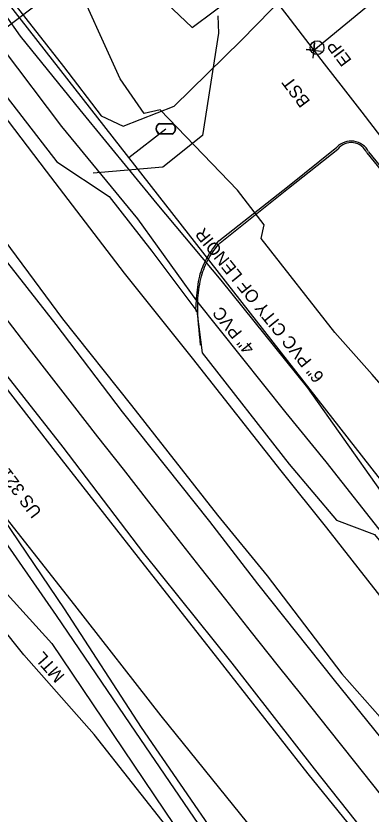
# Model space of a CAD drawing. Extents: x 1263837 to 1268319, y 770628 to 773628.
# Drawn here: x 1266035.1 to 1266148.2, y 772885.8 to 773140.3 of the extents above; entities that cross this region are included whole.
import ezdxf

# ---------------------------------------------------------------- set-up
doc = ezdxf.new("R2010")
doc.units = 0
for name, color, linetype in [('Exist Guardrail', 7, 'Continuous'), ('Exist Guardrail Text', 7, 'Continuous'), ('Exist Property Iron Pin Text', 7, 'Continuous'), ('Exist Roads EOT Text', 7, 'Continuous'), ('Exist Utilities Gas UG Line SUE LOS B', 7, 'Continuous'), ('Exist Utilities Gas UG Line SUE LOS B Text', 7, 'Continuous'), ('Exist Utilities Telephone UG Cable SUE LOS B', 7, 'Continuous'), ('Exist Utilities Telephone UG FO SUE LOS B', 7, 'Continuous'), ('Exist Utilities TV UG Cable SUE LOS B', 7, 'Continuous'), ('Exist Utilities Water Meter CELL', 7, 'Continuous'), ('Exist Utilities Water UG Line SUE LOS B', 7, 'Continuous'), ('Exist Utilities Water UG Line SUE LOS B Text', 7, 'Continuous'), ('Exist Vegetation Woods Line', 7, 'Continuous'), ('Prop Conc 4in Sidewalk', 7, 'Continuous'), ('Prop Drainage Structure Pipe Alternate 42in Label', 7, 'Continuous'), ('Prop Drainage Structure Pipe RCP 60in Class III', 7, 'Continuous'), ('Prop Guardrail', 7, 'Continuous'), ('Prop Horizontal Alignment', 7, 'Continuous'), ('Prop SS Fill Line', 7, 'Continuous'), ('Prop SS Fill Text', 7, 'Continuous'), ('Prop SS Transition Line', 7, 'Continuous'), ('Scratch_Level_2', 7, 'Continuous')]:
    doc.layers.add(name, color=color, linetype=linetype)

# ---------------------------------------------------------------- blocks, each defined once
blk = doc.blocks.new('EXIST PROPERTY IRON PIN')
at = {"layer": 'Prop Conc 4in Sidewalk'}
for radius in [0.0441, 0.00141]:
    blk.add_circle((0, 0), radius, dxfattribs=at)
blk = doc.blocks.new('EXIST UTILITIES WATER METER')
at = {"layer": 'Exist Utilities Water Meter CELL'}
blk.add_line((0, 0), (0, 0), dxfattribs=at)
for points in [[(-0.0408, 0.034), (0.0408, 0.034)], [(-0.0408, 0.0312), (0.0408, 0.0312)], [(0.0408, -0.0312), (-0.0413, -0.0312)], [(0.0408, -0.034), (-0.0413, -0.034)]]:
    blk.add_lwpolyline(points, dxfattribs=at)
for centre, radius, start, end in [((-0.0261, -0.0001), 0.0371, 113.178, 245.9794), ((-0.0259, -0.0001), 0.0347, 115.3009, 243.7824), ((0.0259, 0), 0.0371, 293.6483, 66.3084), ((0.0261, 0), 0.0345, 295.1272, 64.8728)]:
    blk.add_arc(centre, radius, start, end, dxfattribs=at)

msp = doc.modelspace()

# ---------------------------------------------------------------- linework, layer by layer
at = {"layer": 'Exist Guardrail'}
msp.add_lwpolyline([(1266228.54, 772650.54), (1266211.69, 772682.82), (1266194.81, 772714.59), (1266175.46, 772746.94), (1266154.31, 772779.34), (1266140.25, 772802.03), (1266118.08, 772833.91), (1266102.96, 772854.95), (1266084.42, 772880.21), (1266060.03, 772911.15), (1266037.58, 772936.56), (1266030, 772946.04)], dxfattribs=at)
at = {"layer": 'Exist Utilities Gas UG Line SUE LOS B'}
msp.add_lwpolyline([(1266301.62, 772793.02), (1266286.08, 772812.35), (1266262.09, 772842.01), (1266243.02, 772862.25), (1266220.48, 772886.92), (1266195.71, 772919.94), (1266176.51, 772945.32), (1266153.17, 772973.69), (1266133.95, 772998.15), (1266121.2, 773013.77), (1266092.73, 773049.43), (1266073.9, 773075.59), (1266049.68, 773105.06), (1266031.06, 773129.68), (1265993.52, 773179.92)], dxfattribs=at)
at = {"layer": 'Exist Utilities Telephone UG Cable SUE LOS B'}
msp.add_lwpolyline([(1266008.56, 773197.45), (1266009.09, 773190.74), (1266023.54, 773166.8), (1266029.29, 773160.74), (1266032.8, 773146.49), (1266050.24, 773124.2), (1266062.23, 773108.43), (1266069.25, 773105.19), (1266085.51, 773111.53), (1266106.83, 773132.5), (1266131.09, 773157.33)], dxfattribs=at)
at = {"layer": 'Exist Utilities Telephone UG FO SUE LOS B'}
msp.add_lwpolyline([(1266304.09, 772796.95), (1266282.68, 772823.11), (1266259.79, 772851.51), (1266238.02, 772877.36), (1266213.79, 772907.5), (1266201.34, 772925.88), (1266180.67, 772948.97), (1266158.66, 772974.99), (1266151.27, 772988.96), (1266128.09, 773021.69), (1266100.5, 773056.03), (1266080.08, 773080.34), (1266055.55, 773110.31), (1266036.49, 773133.81), (1266017.24, 773161.16), (1265999.24, 773184.25)], dxfattribs=at)
at = {"layer": 'Exist Utilities TV UG Cable SUE LOS B'}
for points in [[(1266037.19, 773158.54), (1266044.2, 773162.17), (1266059.9, 773159.66), (1266076.9, 773150.3), (1266091.19, 773136.64), (1266126.79, 773163.31)], [(1266240.96, 772994.5), (1266228.99, 772979.18), (1266209.71, 772958.7), (1266202.18, 772964.91), (1266178.98, 772993.28), (1266169.92, 773001.47), (1266148.6, 773025.94), (1266136.73, 773039.4), (1266113.26, 773069.37), (1266114.17, 773073.73), (1266105.69, 773084.74), (1266081.06, 773110.3), (1266075.89, 773109.13), (1266068.28, 773120.21), (1266052.48, 773155.25), (1266049, 773158.25), (1266037.19, 773158.54)]]:
    msp.add_lwpolyline(points, dxfattribs=at)
at = {"layer": 'Exist Utilities Water UG Line SUE LOS B'}
msp.add_line((1266071.06, 773095.12), (1266082.82, 773104.31), dxfattribs=at)
msp.add_lwpolyline([(1266307.35, 772809.88), (1266279.02, 772843.7), (1266261.57, 772864.93), (1266241.57, 772883.66), (1266222.07, 772905.04), (1266204.04, 772927.05), (1266182.99, 772951.84), (1266157.71, 772984.17), (1266000.63, 773185.3)], dxfattribs=at)
at = {"layer": 'Exist Vegetation Woods Line'}
msp.add_lwpolyline([(1265737.5, 773343.94), (1265802.41, 773257.53), (1265850.04, 773186.56), (1265870.14, 773156.9), (1265904.49, 773125.47), (1265953.72, 773053.32), (1266023.97, 772964.99), (1266046.51, 772940.19), (1266118.08, 772833.91), (1266225.23, 772647.3), (1266208.09, 772624.42), (1266145.15, 772608.33), (1266113.92, 772610.68), (1266075.12, 772586.17), (1266041.92, 772562.53)], dxfattribs=at)
at = {"layer": 'Prop Drainage Structure Pipe Alternate 42in Label'}
msp.add_line((1266090.78, 773181.4), (1265987.11, 773102.29), dxfattribs=at)
at = {"layer": 'Prop Drainage Structure Pipe RCP 60in Class III'}
msp.add_line((1266130, 773129.33), (1266130, 773129.33), dxfattribs=at)
msp.add_lwpolyline([(1266129.77, 773126.84), (1266130.24, 773131.81), (1266130, 773129.33), (1266127.52, 773129.56), (1266132.49, 773129.09)], dxfattribs=at)
at = {"layer": 'Prop Guardrail'}
for p, q in [((1266130, 773129.33), (1266246.07, 773225.23)), ((1266130.46, 773129.7), (1266131.03, 773130.17))]:
    msp.add_line(p, q, dxfattribs=at)
at = {"layer": 'Prop Horizontal Alignment'}
for radius, end in [(11329.16, 223.309327), (11589.16, 220.45226)]:
    msp.add_arc((1275094.23, 780056.99), radius, 216.983333, end, dxfattribs=at)
at = {"layer": 'Prop SS Fill Line'}
for p, q in [((1266121.95, 773085.33), (1266137.65, 773097.79)), ((1266100.13, 773068), (1266121.95, 773085.33)), ((1266093.83, 773035.33), (1266093.79, 773036.91))]:
    msp.add_line(p, q, dxfattribs=at)
msp.add_lwpolyline([(1266146.91, 773096.6), (1266171.23, 773066.78), (1266193.08, 773039.77), (1266206.58, 773022.9)], dxfattribs=at)
msp.add_ellipse((1266141.94, 773094.54), major_axis=(-0.36, -5.37), ratio=0.999951, start_param=2.031107, end_param=4.130373, dxfattribs=at)
msp.add_spline([(1266093.79, 773036.91), (1266093.08, 773050.27), (1266094.23, 773057.36), (1266096.43, 773062.88), (1266100.13, 773068)], degree=3, dxfattribs=at)
at = {"layer": 'Prop SS Fill Text'}
for p, q in [((1266121.66, 773085.79), (1266137.37, 773098.42)), ((1266099.72, 773068.59), (1266121.66, 773085.79)), ((1266092.64, 773045.98), (1266092.42, 773046.96))]:
    msp.add_line(p, q, dxfattribs=at)
for points in [[(1265928.52, 773196.42), (1265955.6, 773161.07), (1265974.34, 773136.13), (1266000.44, 773102.54), (1266023.03, 773073.42), (1266047.77, 773041.92), (1266068.94, 773014.11), (1266096.74, 772979.15), (1266112.05, 772959.2), (1266136.44, 772928.51), (1266159.7, 772899.76), (1266187.77, 772864.17), (1266215.24, 772830.51), (1266241.66, 772797.95), (1266271.46, 772761.84), (1266300.38, 772726.95), (1266327.38, 772694.6), (1266357.7, 772658.6)], [(1266342.98, 772645.7), (1266315.37, 772675.44), (1266288.09, 772707.47), (1266265.15, 772733.76), (1266237.99, 772767.02), (1266209.88, 772801.17), (1266183.92, 772833.14), (1266156.76, 772866.8), (1266130.22, 772900.23), (1266103.93, 772933.93), (1266075.8, 772969.04), (1266050.1, 773002.76), (1266025.1, 773034.48), (1265999.31, 773067.4), (1265973.53, 773101.82), (1265947.51, 773135.79), (1265921.21, 773170.29), (1265910.51, 773184.53)], [(1265885.83, 773164.94), (1265895.93, 773151.5), (1265922.49, 773116.7), (1265948.57, 773082.02), (1265973.55, 773049.38), (1265999.33, 773015.51), (1266023.22, 772984.57), (1266047.85, 772949.12), (1266073.18, 772911.93), (1266097.79, 772875.76), (1266121.44, 772840.07), (1266145.79, 772804), (1266168.49, 772769), (1266192.41, 772729.79), (1266198.26, 772719.99)], [(1266018.87, 773143.88), (1266020.92, 773129.52), (1266025.71, 773122.64), (1266048.11, 773093.82), (1266064.8, 773082.72), (1266078.4, 773065.24), (1266092.68, 773046.14), (1266094.42, 773032.9), (1266122.13, 772997.34), (1266137.23, 772979.52), (1266149.36, 772974.95), (1266168.03, 772952.31), (1266188.72, 772925.73), (1266194.52, 772906.56), (1266212.5, 772883.55), (1266239.16, 772850.91), (1266256.4, 772829.38), (1266270.86, 772824.48), (1266285.94, 772806.2), (1266301.1, 772787.97), (1266304.68, 772771.64), (1266323.99, 772746.86), (1266350.83, 772714.9)], [(1266099.4, 773140.28), (1266099.67, 773134.81), (1266094.55, 773102.14), (1266081.87, 773092.1), (1266059.64, 773090.16)], [(1266147.47, 773096.94), (1266171.67, 773067.18), (1266193.45, 773040.19), (1266206.97, 773023.28)]]:
    msp.add_lwpolyline(points, dxfattribs=at)
msp.add_ellipse((1266141.9, 773094.13), major_axis=(-6.23, -0.43), ratio=0.999862, start_param=3.540429, end_param=5.456365, dxfattribs=at)
msp.add_spline([(1266092.42, 773046.96), (1266092.65, 773050.29), (1266093.62, 773057.3), (1266095.93, 773063.06), (1266099.72, 773068.59)], degree=3, dxfattribs=at)
at = {"layer": 'Prop SS Transition Line'}
for points in [[(1265951.1, 773213.35), (1265978.42, 773176.6), (1265997.02, 773153.03), (1266022.4, 773120), (1266044.65, 773090.78), (1266069.51, 773058.32), (1266091.23, 773031.16), (1266119.47, 772995.3), (1266134.06, 772977.06), (1266160.18, 772943.7), (1266181.04, 772918.53), (1266210.29, 772881.31), (1266236.57, 772849.23), (1266263.03, 772815.74), (1266292.51, 772780.33), (1266321.33, 772744.69), (1266348.53, 772712.94), (1266379.06, 772676.58)], [(1265931.75, 773198.41), (1265958.44, 773163.08), (1265977.34, 773138.21), (1266002.74, 773104.7), (1266026, 773075.89), (1266049.89, 773043.76), (1266071.92, 773016.05), (1266099.33, 772981.13), (1266115.17, 772961.77), (1266138.92, 772930.58), (1266163.31, 772902.93), (1266190.56, 772866.23), (1266218.32, 772833.09), (1266244.06, 772800), (1266274.56, 772764.58), (1266302.88, 772729.04), (1266330.2, 772696.89), (1266360.46, 772660.78)], [(1266340.35, 772643.75), (1266313.04, 772673.58), (1266286.11, 772706.13), (1266263.29, 772731.91), (1266236.02, 772765.56), (1266208.12, 772799.58), (1266182.09, 772831.47), (1266155.08, 772865.48), (1266128.15, 772898.64), (1266101.77, 772932.49), (1266074.07, 772967.59), (1266047.71, 773001.38), (1266023.12, 773032.97), (1265997.85, 773066.28), (1265971.87, 773100.61), (1265945.83, 773134.57), (1265919.72, 773169.02), (1265908.62, 773183.23)], [(1265888.84, 773167.72), (1265899.08, 773154.02), (1265925.44, 773119.23), (1265951.93, 773084.95), (1265976.91, 773051.94), (1266002.65, 773018.15), (1266026.14, 772987.06), (1266050.41, 772951.25), (1266074.99, 772913.45), (1266099.86, 772877.32), (1266123.47, 772841.56), (1266147.62, 772805.29), (1266170.13, 772770.51), (1266194.51, 772731.35), (1266200.38, 772721.09), (1266213.55, 772697.82)], [(1266320.98, 772626.86), (1266293.88, 772658.2), (1266267.08, 772689.36), (1266244.17, 772715.92), (1266216.25, 772749.76), (1266188.22, 772783.86), (1266177.32, 772797.29), (1266151.45, 772829.79), (1266135.22, 772850.34), (1266108.99, 772882.94), (1266081.36, 772917.14), (1266053.8, 772952.46), (1266026.04, 772987.75)]]:
    msp.add_lwpolyline(points, dxfattribs=at)
at = {"layer": 'Scratch_Level_2'}
msp.add_arc((1275094.23, 780056.99), 11459.16, 216.983333, 225.433333, dxfattribs=at)

# ---------------------------------------------------------------- block references
at = {"layer": 'Exist Utilities Water Meter CELL', "xscale": 50, "yscale": 50}
msp.add_blockref('EXIST UTILITIES WATER METER', (1266082.82, 773104.31), dxfattribs=at)
at = {"layer": 'Prop Conc 4in Sidewalk', "xscale": 50, "yscale": 50}
msp.add_blockref('EXIST PROPERTY IRON PIN', (1266131.03, 773130.17), dxfattribs=at)

# ---------------------------------------------------------------- texts
at = {"layer": 'Exist Guardrail Text'}
msp.add_text('MTL', height=4, rotation=131.443, dxfattribs=at).set_placement((1266050.82, 772929.94))
at = {"layer": 'Exist Property Iron Pin Text'}
msp.add_text('EIP', height=4, rotation=126.9057, dxfattribs=at).set_placement((1266142.23, 773126.13))
at = {"layer": 'Exist Roads EOT Text'}
for s, p in [('BST', (1266129.02, 773113.04)), ('US 321 (HICKORY BLVD.)', (1266043.49, 772982.15))]:
    msp.add_text(s, height=4, rotation=126.9057, dxfattribs=at).set_placement(p)
at = {"layer": 'Exist Utilities Gas UG Line SUE LOS B Text'}
msp.add_text('4" PVC', height=4, rotation=128.6055, dxfattribs=at).set_placement((1266111.34, 773034.42))
at = {"layer": 'Exist Utilities Water UG Line SUE LOS B Text'}
msp.add_text('6" PVC CITY OF LENOIR', height=4, rotation=128.8956, dxfattribs=at).set_placement((1266133.5, 773025.38))

doc.saveas('drawing.dxf')
